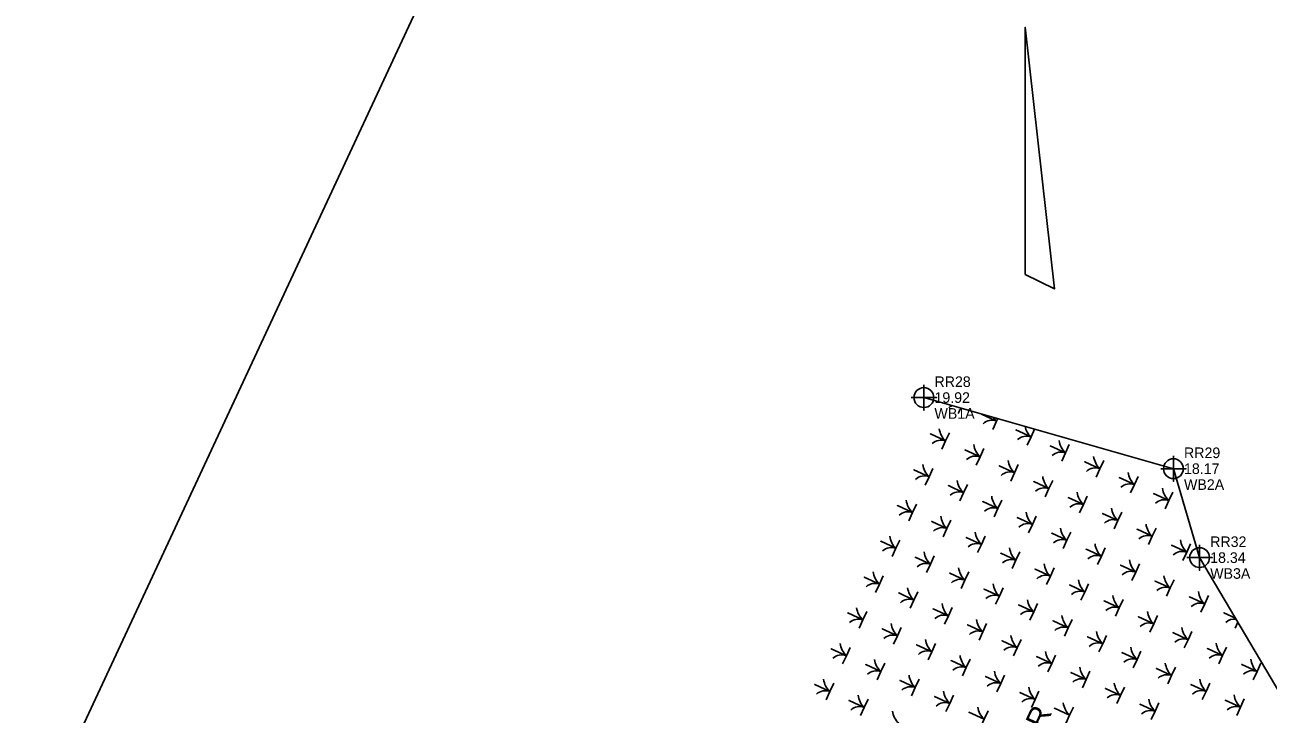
# Model space of a CAD drawing. Extents: x 2532037 to 2533565, y 713396 to 716867.
# Drawn here: x 2532529.2 to 2532822.3, y 715817.2 to 715979.9 of the extents above; entities that cross this region are included whole.
import ezdxf

# ---------------------------------------------------------------- set-up
doc = ezdxf.new("R2010")
doc.units = 0
for name, color, linetype in [('CTL North Arrow NAD 83 NA 2011 CELL', 7, 'Continuous'), ('Exist Environmental Wetland Boundary', 7, 'Continuous'), ('Exist Environmental Wetland Boundary Cogo Comment', 7, 'Continuous'), ('Exist Environmental Wetland Boundary Cogo Elevation', 7, 'Continuous'), ('Exist Environmental Wetland Boundary Cogo Number', 7, 'Continuous'), ('Exist Environmental Wetland Boundary Cogo Point CELL', 7, 'Continuous'), ('Exist Property Owner Text', 7, 'Continuous'), ('Scratch_Level_1', 7, 'Continuous'), ('Sheet PDF Layout', 7, 'Continuous')]:
    doc.layers.add(name, color=color, linetype=linetype)

msp = doc.modelspace()

# ---------------------------------------------------------------- linework, layer by layer
at = {"layer": 'CTL North Arrow NAD 83 NA 2011 CELL'}
msp.add_lwpolyline([(2532765.01, 715920.98), (2532771.88, 715917.57), (2532765.01, 715979.3)], close=True, dxfattribs=at)
at = {"layer": 'Exist Environmental Wetland Boundary'}
for p, q in [((2532741.11, 715891.92), (2532799.94, 715875.14)), ((2532799.94, 715875.14), (2532806.11, 715854.16)), ((2532806.11, 715854.16), (2532825.29, 715821.82))]:
    msp.add_line(p, q, dxfattribs=at)
at = {"layer": 'Exist Environmental Wetland Boundary Cogo Point CELL'}
for points in [[(2532741.11, 715894.92), (2532741.11, 715888.92), (2532741.11, 715891.92), (2532744.11, 715891.92), (2532738.11, 715891.92)], [(2532799.94, 715878.14), (2532799.94, 715872.14), (2532799.94, 715875.14), (2532802.94, 715875.14), (2532796.94, 715875.14)], [(2532806.11, 715857.16), (2532806.11, 715851.16), (2532806.11, 715854.16), (2532809.11, 715854.16), (2532803.11, 715854.16)]]:
    msp.add_lwpolyline(points, dxfattribs=at)
for centre in [(2532741.11, 715891.92), (2532799.94, 715875.14), (2532806.11, 715854.16)]:
    msp.add_circle(centre, 2.34, dxfattribs=at)
at = {"layer": 'Scratch_Level_1'}
for p, q in [((2532749.23, 715888.17), (2532749.82, 715889.44)), ((2532814.53, 715837.54), (2532815.16, 715838.9))]:
    msp.add_line(p, q, dxfattribs=at)
for points in [[(2532757.36, 715884.42), (2532758.26, 715886.37), (2532754.68, 715888.03), (2532758.26, 715886.37), (2532758.52, 715886.95)], [(2532745.34, 715879.73), (2532746.24, 715881.68), (2532742.66, 715883.33), (2532746.24, 715881.68), (2532747.14, 715883.63)], [(2532765.48, 715880.67), (2532766.38, 715882.62), (2532762.8, 715884.28), (2532766.38, 715882.62), (2532767.23, 715884.47)], [(2532753.46, 715875.98), (2532754.36, 715877.93), (2532750.78, 715879.58), (2532754.36, 715877.93), (2532755.26, 715879.88)], [(2532773.6, 715876.92), (2532774.5, 715878.87), (2532770.92, 715880.53), (2532774.5, 715878.87), (2532775.4, 715880.83)], [(2532781.72, 715873.17), (2532782.62, 715875.13), (2532779.04, 715876.78), (2532782.62, 715875.13), (2532783.52, 715877.08)], [(2532741.44, 715871.28), (2532742.34, 715873.23), (2532738.76, 715874.89), (2532742.34, 715873.23), (2532743.24, 715875.19)], [(2532761.58, 715872.23), (2532762.48, 715874.18), (2532758.9, 715875.83), (2532762.48, 715874.18), (2532763.38, 715876.13)], [(2532749.56, 715867.53), (2532750.46, 715869.48), (2532746.88, 715871.14), (2532750.46, 715869.48), (2532751.36, 715871.44)], [(2532769.7, 715868.48), (2532770.6, 715870.43), (2532767.02, 715872.08), (2532770.6, 715870.43), (2532771.5, 715872.38)], [(2532789.84, 715869.42), (2532790.74, 715871.38), (2532787.16, 715873.03), (2532790.74, 715871.38), (2532791.64, 715873.33)], [(2532777.82, 715864.73), (2532778.72, 715866.68), (2532775.14, 715868.33), (2532778.72, 715866.68), (2532779.62, 715868.63)], [(2532797.96, 715865.67), (2532798.86, 715867.63), (2532795.28, 715869.28), (2532798.86, 715867.63), (2532799.77, 715869.58)], [(2532737.54, 715862.84), (2532738.44, 715864.79), (2532734.86, 715866.44), (2532738.44, 715864.79), (2532739.34, 715866.74)], [(2532757.68, 715863.78), (2532758.58, 715865.74), (2532755, 715867.39), (2532758.58, 715865.74), (2532759.48, 715867.69)], [(2532785.94, 715860.98), (2532786.84, 715862.93), (2532783.26, 715864.59), (2532786.84, 715862.93), (2532787.75, 715864.88)], [(2532745.66, 715859.09), (2532746.56, 715861.04), (2532742.98, 715862.69), (2532746.56, 715861.04), (2532747.46, 715862.99)], [(2532765.8, 715860.03), (2532766.7, 715861.99), (2532763.12, 715863.64), (2532766.7, 715861.99), (2532767.6, 715863.94)], [(2532753.78, 715855.34), (2532754.68, 715857.29), (2532751.1, 715858.94), (2532754.68, 715857.29), (2532755.58, 715859.24)], [(2532773.92, 715856.28), (2532774.82, 715858.24), (2532771.24, 715859.89), (2532774.82, 715858.24), (2532775.73, 715860.19)], [(2532794.06, 715857.23), (2532794.97, 715859.18), (2532791.38, 715860.84), (2532794.97, 715859.18), (2532795.87, 715861.13)], [(2532733.64, 715854.39), (2532734.54, 715856.35), (2532730.96, 715858), (2532734.54, 715856.35), (2532735.44, 715858.3)], [(2532782.04, 715852.54), (2532782.95, 715854.49), (2532779.36, 715856.14), (2532782.95, 715854.49), (2532783.85, 715856.44)], [(2532802.19, 715853.48), (2532803.09, 715855.43), (2532799.51, 715857.09), (2532803.09, 715855.43), (2532803.99, 715857.39)], [(2532741.76, 715850.64), (2532742.66, 715852.6), (2532739.08, 715854.25), (2532742.66, 715852.6), (2532743.56, 715854.55)], [(2532761.9, 715851.59), (2532762.8, 715853.54), (2532759.22, 715855.2), (2532762.8, 715853.54), (2532763.71, 715855.49)], [(2532749.88, 715846.89), (2532750.78, 715848.85), (2532747.2, 715850.5), (2532750.78, 715848.85), (2532751.69, 715850.8)], [(2532770.02, 715847.84), (2532770.93, 715849.79), (2532767.34, 715851.45), (2532770.93, 715849.79), (2532771.83, 715851.74)], [(2532790.17, 715848.79), (2532791.07, 715850.74), (2532787.49, 715852.39), (2532791.07, 715850.74), (2532791.97, 715852.69)], [(2532729.74, 715845.95), (2532730.64, 715847.9), (2532727.06, 715849.55), (2532730.64, 715847.9), (2532731.54, 715849.85)], [(2532778.15, 715844.09), (2532779.05, 715846.04), (2532775.47, 715847.7), (2532779.05, 715846.04), (2532779.95, 715848)], [(2532798.29, 715845.04), (2532799.19, 715846.99), (2532795.61, 715848.64), (2532799.19, 715846.99), (2532800.09, 715848.94)], [(2532737.86, 715842.2), (2532738.76, 715844.15), (2532735.18, 715845.81), (2532738.76, 715844.15), (2532739.67, 715846.1)], [(2532758, 715843.15), (2532758.91, 715845.1), (2532755.32, 715846.75), (2532758.91, 715845.1), (2532759.81, 715847.05)], [(2532806.41, 715841.29), (2532807.31, 715843.24), (2532803.73, 715844.89), (2532807.31, 715843.24), (2532808.21, 715845.19)], [(2532745.99, 715838.45), (2532746.89, 715840.4), (2532743.3, 715842.06), (2532746.89, 715840.4), (2532747.79, 715842.35)], [(2532766.13, 715839.4), (2532767.03, 715841.35), (2532763.45, 715843), (2532767.03, 715841.35), (2532767.93, 715843.3)], [(2532786.27, 715840.34), (2532787.17, 715842.29), (2532783.59, 715843.95), (2532787.17, 715842.29), (2532788.07, 715844.25)], [(2532725.84, 715837.5), (2532726.75, 715839.46), (2532723.16, 715841.11), (2532726.75, 715839.46), (2532727.65, 715841.41)], [(2532754.11, 715834.7), (2532755.01, 715836.65), (2532751.43, 715838.31), (2532755.01, 715836.65), (2532755.91, 715838.61)], [(2532774.25, 715835.65), (2532775.15, 715837.6), (2532771.57, 715839.25), (2532775.15, 715837.6), (2532776.05, 715839.55)], [(2532794.39, 715836.59), (2532795.29, 715838.54), (2532791.71, 715840.2), (2532795.29, 715838.54), (2532796.19, 715840.5)], [(2532814.58, 715839.88), (2532811.85, 715841.14), (2532814.58, 715839.88)], [(2532733.97, 715833.76), (2532734.87, 715835.71), (2532731.28, 715837.36), (2532734.87, 715835.71), (2532735.77, 715837.66)], [(2532782.37, 715831.9), (2532783.27, 715833.85), (2532779.69, 715835.5), (2532783.27, 715833.85), (2532784.17, 715835.8)], [(2532802.51, 715832.84), (2532803.41, 715834.79), (2532799.83, 715836.45), (2532803.41, 715834.79), (2532804.31, 715836.75)], [(2532721.95, 715829.06), (2532722.85, 715831.01), (2532719.26, 715832.67), (2532722.85, 715831.01), (2532723.75, 715832.96)], [(2532742.09, 715830.01), (2532742.99, 715831.96), (2532739.41, 715833.61), (2532742.99, 715831.96), (2532743.89, 715833.91)], [(2532762.23, 715830.95), (2532763.13, 715832.9), (2532759.55, 715834.56), (2532763.13, 715832.9), (2532764.03, 715834.86)], [(2532810.63, 715829.09), (2532811.53, 715831.05), (2532807.95, 715832.7), (2532811.53, 715831.05), (2532812.43, 715833)], [(2532750.21, 715826.26), (2532751.11, 715828.21), (2532747.53, 715829.86), (2532751.11, 715828.21), (2532752.01, 715830.16)], [(2532770.35, 715827.2), (2532771.25, 715829.15), (2532767.67, 715830.81), (2532771.25, 715829.15), (2532772.15, 715831.11)], [(2532790.49, 715828.15), (2532791.39, 715830.1), (2532787.81, 715831.75), (2532791.39, 715830.1), (2532792.29, 715832.05)], [(2532730.07, 715825.31), (2532730.97, 715827.26), (2532727.39, 715828.92), (2532730.97, 715827.26), (2532731.87, 715829.22)], [(2532778.47, 715823.45), (2532779.37, 715825.4), (2532775.79, 715827.06), (2532779.37, 715825.4), (2532780.27, 715827.36)], [(2532798.61, 715824.4), (2532799.51, 715826.35), (2532795.93, 715828), (2532799.51, 715826.35), (2532800.41, 715828.3)], [(2532818.75, 715825.34), (2532819.65, 715827.3), (2532816.07, 715828.95), (2532819.65, 715827.3), (2532820.56, 715829.25)], [(2532718.05, 715820.62), (2532718.95, 715822.57), (2532715.37, 715824.22), (2532718.95, 715822.57), (2532719.85, 715824.52)], [(2532738.19, 715821.56), (2532739.09, 715823.51), (2532735.51, 715825.17), (2532739.09, 715823.51), (2532739.99, 715825.47)], [(2532758.33, 715822.51), (2532759.23, 715824.46), (2532755.65, 715826.11), (2532759.23, 715824.46), (2532760.13, 715826.41)], [(2532806.73, 715820.65), (2532807.63, 715822.6), (2532804.05, 715824.25), (2532807.63, 715822.6), (2532808.54, 715824.55)], [(2532746.31, 715817.81), (2532747.21, 715819.76), (2532743.63, 715821.42), (2532747.21, 715819.76), (2532748.11, 715821.72)], [(2532766.45, 715818.76), (2532767.35, 715820.71), (2532763.77, 715822.36), (2532767.35, 715820.71), (2532768.25, 715822.66)], [(2532786.59, 715819.7), (2532787.49, 715821.66), (2532783.91, 715823.31), (2532787.49, 715821.66), (2532788.39, 715823.61)], [(2532726.17, 715816.87), (2532727.07, 715818.82), (2532723.49, 715820.47), (2532727.07, 715818.82), (2532727.97, 715820.77)], [(2532774.57, 715815.01), (2532775.47, 715816.96), (2532771.89, 715818.61), (2532775.47, 715816.96), (2532776.38, 715818.91)], [(2532794.71, 715815.95), (2532795.62, 715817.91), (2532792.03, 715819.56), (2532795.62, 715817.91), (2532796.52, 715819.86)], [(2532814.86, 715816.9), (2532815.76, 715818.85), (2532812.17, 715820.51), (2532815.76, 715818.85), (2532816.66, 715820.8)], [(2532754.43, 715814.06), (2532755.33, 715816.02), (2532751.75, 715817.67), (2532755.33, 715816.02), (2532756.23, 715817.97)]]:
    msp.add_lwpolyline(points, dxfattribs=at)
for centre, radius, start, end in [((2532749.05, 715887.25), 3.07, 115.1732, 132.7539), ((2532757.17, 715883.5), 3.07, 69.3593, 132.7539), ((2532761.54, 715889.88), 4.81, 213.358, 226.8412), ((2532749.52, 715885.18), 4.81, 187.3464, 226.8412), ((2532765.29, 715879.75), 3.07, 69.3593, 132.7539), ((2532769.67, 715886.13), 4.81, 192.1923, 226.8412), ((2532745.15, 715878.8), 3.07, 69.3593, 132.7539), ((2532757.65, 715881.43), 4.81, 187.3464, 226.8412), ((2532777.79, 715882.38), 4.81, 187.3464, 226.8412), ((2532753.27, 715875.05), 3.07, 69.3593, 132.7539), ((2532765.77, 715877.69), 4.81, 187.3464, 226.8412), ((2532773.42, 715876), 3.07, 69.3593, 132.7539), ((2532785.91, 715878.63), 4.81, 187.3464, 226.8412), ((2532745.63, 715876.74), 4.81, 187.3464, 226.8412), ((2532761.4, 715871.3), 3.07, 69.3593, 132.7539), ((2532781.54, 715872.25), 3.07, 69.3593, 132.7539), ((2532794.03, 715874.88), 4.81, 187.3464, 226.8412), ((2532741.26, 715870.36), 3.07, 69.3593, 132.7539), ((2532753.75, 715872.99), 4.81, 187.3464, 226.8412), ((2532773.89, 715873.94), 4.81, 187.3464, 226.8412), ((2532789.66, 715868.5), 3.07, 69.3593, 132.7539), ((2532749.38, 715866.61), 3.07, 69.3593, 132.7539), ((2532761.87, 715869.24), 4.81, 187.3464, 226.8412), ((2532769.52, 715867.55), 3.07, 69.3593, 132.7539), ((2532782.01, 715870.19), 4.81, 187.3464, 226.8412), ((2532797.78, 715864.75), 3.07, 69.3593, 132.7539), ((2532802.15, 715871.13), 4.81, 187.3464, 226.8412), ((2532737.36, 715861.91), 3.07, 69.3593, 132.7539), ((2532741.73, 715868.3), 4.81, 187.3464, 226.8412), ((2532757.5, 715862.86), 3.07, 69.3593, 132.7539), ((2532769.99, 715865.49), 4.81, 187.3464, 226.8412), ((2532777.64, 715863.8), 3.07, 69.3593, 132.7539), ((2532790.13, 715866.44), 4.81, 187.3464, 226.8412), ((2532749.85, 715864.55), 4.81, 187.3464, 226.8412), ((2532765.62, 715859.11), 3.07, 69.3593, 132.7539), ((2532785.76, 715860.05), 3.07, 69.3593, 132.7539), ((2532798.25, 715862.69), 4.81, 187.3464, 226.8412), ((2532737.83, 715859.85), 4.81, 187.3464, 226.8412), ((2532745.48, 715858.16), 3.07, 69.3593, 132.7539), ((2532757.97, 715860.8), 4.81, 187.3464, 226.8412), ((2532778.11, 715861.74), 4.81, 187.3464, 226.8412), ((2532793.88, 715856.31), 3.07, 69.3593, 132.7539), ((2532733.46, 715853.47), 3.07, 69.3593, 132.7539), ((2532753.6, 715854.41), 3.07, 69.3593, 132.7539), ((2532766.09, 715857.05), 4.81, 187.3464, 226.8412), ((2532773.74, 715855.36), 3.07, 69.3593, 132.7539), ((2532786.23, 715857.99), 4.81, 187.3464, 226.8412), ((2532806.37, 715858.94), 4.81, 187.3464, 226.8412), ((2532745.95, 715856.1), 4.81, 187.3464, 226.8412), ((2532761.72, 715850.66), 3.07, 69.3593, 132.7539), ((2532781.86, 715851.61), 3.07, 69.3593, 132.7539), ((2532794.35, 715854.24), 4.81, 187.3464, 226.8412), ((2532802, 715852.56), 3.07, 69.3593, 132.7539), ((2532733.93, 715851.41), 4.81, 187.3464, 226.8412), ((2532741.58, 715849.72), 3.07, 69.3593, 132.7539), ((2532754.07, 715852.35), 4.81, 187.3464, 226.8412), ((2532774.21, 715853.3), 4.81, 187.3464, 226.8412), ((2532789.98, 715847.86), 3.07, 69.3593, 132.7539), ((2532729.56, 715845.02), 3.07, 69.3593, 132.7539), ((2532749.7, 715845.97), 3.07, 69.3593, 132.7539), ((2532762.19, 715848.6), 4.81, 187.3464, 226.8412), ((2532769.84, 715846.92), 3.07, 69.3593, 132.7539), ((2532782.33, 715849.55), 4.81, 187.3464, 226.8412), ((2532802.48, 715850.49), 4.81, 187.3464, 226.8412), ((2532737.68, 715841.27), 3.07, 69.3593, 132.7539), ((2532742.05, 715847.66), 4.81, 187.3464, 226.8412), ((2532757.82, 715842.22), 3.07, 69.3593, 132.7539), ((2532777.96, 715843.17), 3.07, 69.3593, 132.7539), ((2532790.46, 715845.8), 4.81, 187.3464, 226.8412), ((2532798.11, 715844.11), 3.07, 69.3593, 132.7539), ((2532810.6, 715846.74), 4.81, 187.3464, 226.8412), ((2532730.03, 715842.96), 4.81, 187.3464, 226.8412), ((2532750.17, 715843.91), 4.81, 187.3464, 226.8412), ((2532765.94, 715838.47), 3.07, 69.3593, 132.7539), ((2532770.31, 715844.85), 4.81, 187.3464, 226.8412), ((2532786.09, 715839.42), 3.07, 69.3593, 132.7539), ((2532798.58, 715842.05), 4.81, 187.3464, 226.8412), ((2532806.23, 715840.36), 3.07, 69.3593, 132.7539), ((2532725.66, 715836.58), 3.07, 69.3593, 132.7539), ((2532738.15, 715839.21), 4.81, 187.3464, 226.8412), ((2532745.8, 715837.53), 3.07, 69.3593, 132.7539), ((2532758.3, 715840.16), 4.81, 187.3464, 226.8412), ((2532778.44, 715841.1), 4.81, 187.3464, 226.8412), ((2532794.21, 715835.67), 3.07, 69.3593, 132.7539), ((2532814.35, 715836.61), 3.07, 83.2738, 132.7539), ((2532733.78, 715832.83), 3.07, 69.3593, 132.7539), ((2532753.92, 715833.78), 3.07, 69.3593, 132.7539), ((2532766.42, 715836.41), 4.81, 187.3464, 226.8412), ((2532774.07, 715834.72), 3.07, 69.3593, 132.7539), ((2532786.56, 715837.35), 4.81, 187.3464, 226.8412), ((2532806.7, 715838.3), 4.81, 187.3464, 226.8412), ((2532726.13, 715834.52), 4.81, 187.3464, 226.8412), ((2532746.28, 715835.46), 4.81, 187.3464, 226.8412), ((2532762.05, 715830.03), 3.07, 69.3593, 132.7539), ((2532782.19, 715830.97), 3.07, 69.3593, 132.7539), ((2532794.68, 715833.61), 4.81, 187.3464, 226.8412), ((2532802.33, 715831.92), 3.07, 69.3593, 132.7539), ((2532814.82, 715834.55), 4.81, 187.3464, 226.8412), ((2532721.76, 715828.14), 3.07, 69.3593, 132.7539), ((2532734.26, 715830.77), 4.81, 187.3464, 226.8412), ((2532741.9, 715829.08), 3.07, 69.3593, 132.7539), ((2532754.4, 715831.71), 4.81, 187.3464, 226.8412), ((2532774.54, 715832.66), 4.81, 187.3464, 226.8412), ((2532790.31, 715827.22), 3.07, 69.3593, 132.7539), ((2532810.45, 715828.17), 3.07, 69.3593, 132.7539), ((2532822.94, 715830.8), 4.81, 187.3464, 226.8412), ((2532729.88, 715824.39), 3.07, 69.3593, 132.7539), ((2532750.03, 715825.33), 3.07, 69.3593, 132.7539), ((2532762.52, 715827.96), 4.81, 187.3464, 226.8412), ((2532770.17, 715826.28), 3.07, 69.3593, 132.7539), ((2532782.66, 715828.91), 4.81, 187.3464, 226.8412), ((2532802.8, 715829.86), 4.81, 187.3464, 226.8412), ((2532818.57, 715824.42), 3.07, 69.3593, 132.7539), ((2532722.24, 715826.07), 4.81, 187.3464, 226.8412), ((2532742.38, 715827.02), 4.81, 187.3464, 226.8412), ((2532758.15, 715821.58), 3.07, 69.3593, 132.7539), ((2532778.29, 715822.53), 3.07, 69.3593, 132.7539), ((2532790.78, 715825.16), 4.81, 187.3464, 226.8412), ((2532798.43, 715823.47), 3.07, 69.3593, 132.7539), ((2532810.92, 715826.11), 4.81, 187.3464, 226.8412), ((2532717.86, 715819.69), 3.07, 69.3593, 132.7539), ((2532730.36, 715822.32), 4.81, 187.3464, 226.8412), ((2532738.01, 715820.64), 3.07, 69.3593, 132.7539), ((2532750.5, 715823.27), 4.81, 187.3464, 226.8412), ((2532766.27, 715817.83), 3.07, 69.3593, 132.7539), ((2532770.64, 715824.22), 4.81, 187.3464, 226.8412), ((2532786.41, 715818.78), 3.07, 69.3593, 132.7539), ((2532806.55, 715819.72), 3.07, 69.3593, 132.7539), ((2532819.04, 715822.36), 4.81, 187.3464, 226.8412), ((2532725.99, 715815.94), 3.07, 69.3593, 132.7539), ((2532746.13, 715816.89), 3.07, 69.3593, 132.7539), ((2532758.62, 715819.52), 4.81, 187.3464, 226.8412), ((2532778.76, 715820.47), 4.81, 187.3464, 226.8412), ((2532794.53, 715815.03), 3.07, 69.3593, 132.7539), ((2532798.9, 715821.41), 4.81, 187.3464, 226.8412), ((2532814.67, 715815.97), 3.07, 69.3593, 132.7539), ((2532738.48, 715818.57), 4.81, 187.3464, 226.8412)]:
    msp.add_arc(centre, radius, start, end, dxfattribs=at)
at = {"layer": 'Sheet PDF Layout'}
msp.add_line((2532199.09, 715075.6), (2532767.38, 716297.08), dxfattribs=at)

# ---------------------------------------------------------------- texts
at = {"layer": 'Exist Environmental Wetland Boundary Cogo Comment'}
for s, p in [('WB1A', (2532743.61, 715886.92)), ('WB2A', (2532802.44, 715870.14)), ('WB3A', (2532808.61, 715849.16))]:
    msp.add_text(s, height=2.5, dxfattribs=at).set_placement(p)
at = {"layer": 'Exist Environmental Wetland Boundary Cogo Elevation'}
for s, p in [('19.92', (2532743.61, 715890.67)), ('18.17', (2532802.44, 715873.89)), ('18.34', (2532808.61, 715852.91))]:
    msp.add_text(s, height=2.5, dxfattribs=at).set_placement(p)
at = {"layer": 'Exist Environmental Wetland Boundary Cogo Number'}
for s, p in [('RR28', (2532743.61, 715894.42)), ('RR29', (2532802.44, 715877.64)), ('RR32', (2532808.61, 715856.66))]:
    msp.add_text(s, height=2.5, dxfattribs=at).set_placement(p)
at = {"layer": 'Exist Property Owner Text'}
msp.add_text('JOE S SHRADER', height=5, rotation=65.05, dxfattribs=at).set_placement((2532748.73, 715768.87))

doc.saveas('drawing.dxf')
